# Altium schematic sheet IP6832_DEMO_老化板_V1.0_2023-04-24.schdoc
size 304 x 179 mm
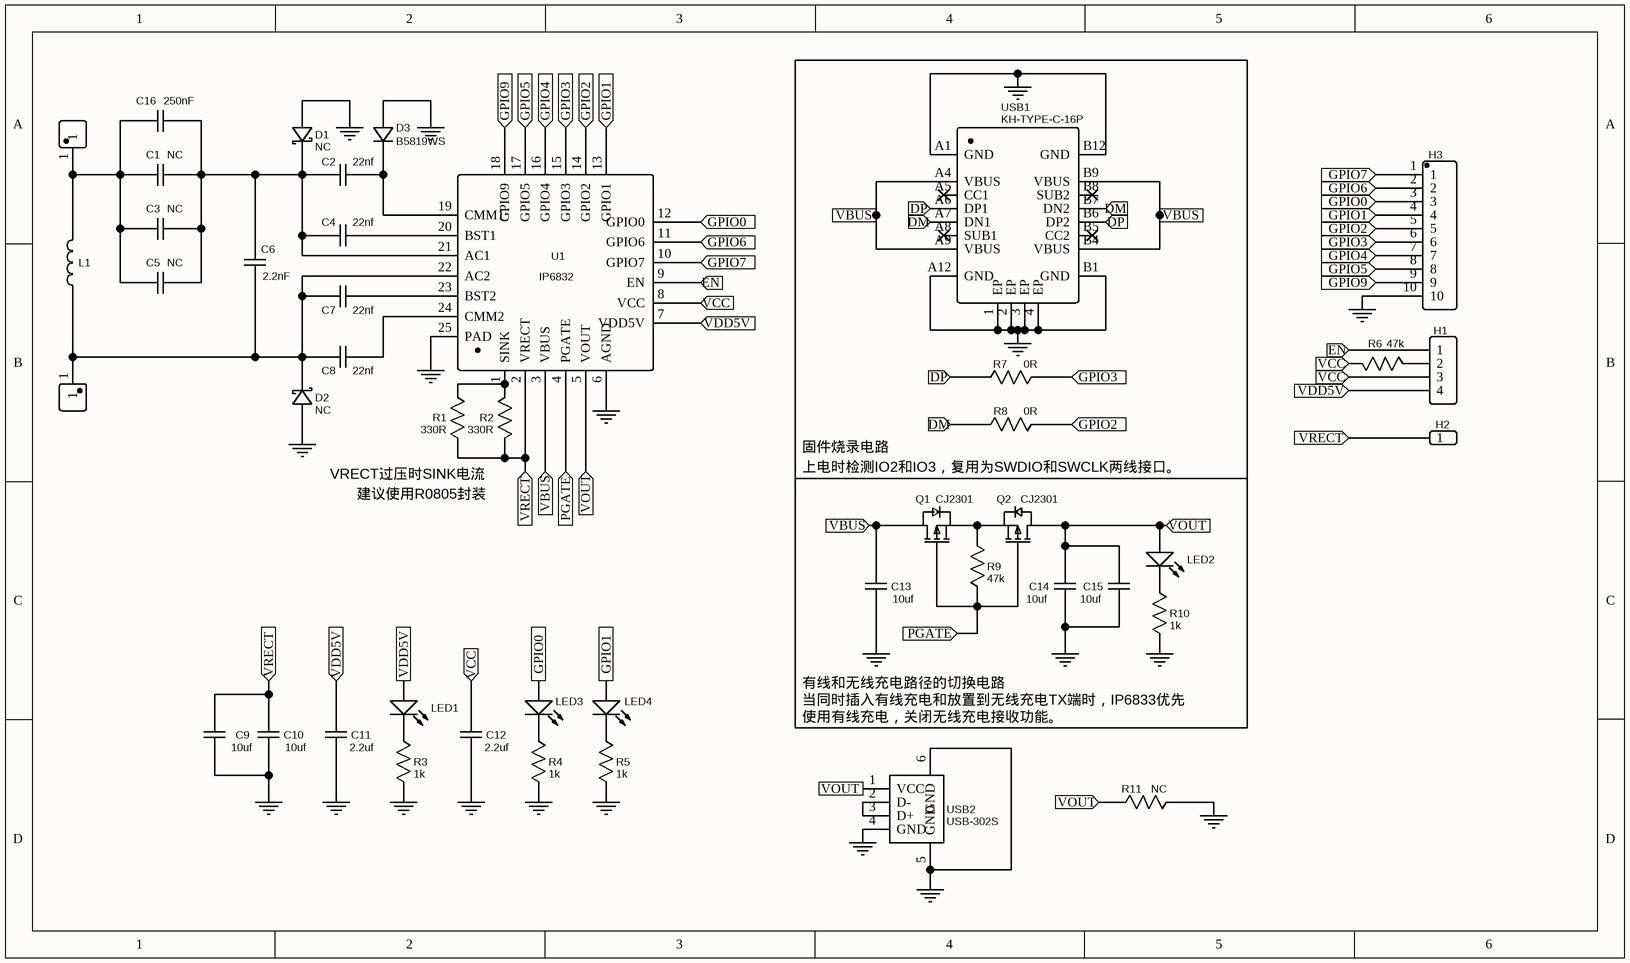
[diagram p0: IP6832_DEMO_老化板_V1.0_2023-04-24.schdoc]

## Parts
C1  NC  [C0603]
C2  22nf  [C0603]
C3  NC  [C0603]
C4  22nf  [C0603]
C5  NC  [C0603]
C6  2.2nF  [C0603]
C7  22nf  [C0603]
C8  22nf  [C0603]
C9  10uf  [C0603]
C10  10uf  [C0603]
C11  2.2uf  [C0603]
C12  2.2uf  [C0603]
C13  10uf  [C0603]
C14  10uf  [C0603]
C15  10uf  [C0603]
C16  250nF  [CAP-TH_L15-W9-P7.50-D0.6]
D1  NC  [SOD-123FL_L2.8-W1.8-LS3.8-R-RD]
D2  NC  [SOD-123FL_L2.8-W1.8-LS3.8-R-RD]
D3  B5819WS  [SOD-323_L1.8-W1.3-LS2.5-RD]
H1  HDR-M-2.54_1x4  [HDR-M-2.54_1X4]  (value not drawn)
H2  Header-Male-2.54_1x1  [HDR-TH_1P-P2.54-V-M]  (value not drawn)
H3  Header-Male-2.54_1x10  [HDR-TH_10P-P2.54-V-M-1]  (value not drawn)
L1  10uH  [IND-SMD_L6.4-W4.1]  (value not drawn)
LED1  LED  [LED0603_RED]  (value not drawn)
LED2  LED  [LED0603_RED]  (value not drawn)
LED3  LED  [LED0603_RED]  (value not drawn)
LED4  LED  [LED0603_RED]  (value not drawn)
Q1  CJ2301  [SOT-23-3_L2.9-W1.3-P1.90-LS2.4-BR]
Q2  CJ2301  [SOT-23-3_L2.9-W1.3-P1.90-LS2.4-BR]
R1  330R  [R0805]
R2  330R  [R0805]
R3  1k  [R0603]
R4  1k  [R0603]
R5  1k  [R0603]
R6  47k  [R0603]
R7  0R  [R0603]
R8  0R  [R0603]
R9  47k  [R0603]
R10  1k  [R0603]
R11  NC  [R_P55]
U1  IP6832  [QFN-24_L4.0-W4.0-P0.50-BL-EP2.5]
U2  TP  [TESTPOINT-TH_BD3.2]  (value not drawn)
U3  TP  [TESTPOINT-TH_BD3.2]  (value not drawn)
USB1  KH-TYPE-C-16P  [USB-C-SMD_KH-TYPE-C-16P]
USB2  USB-302S  [USB-A-SMD_USB-302S]

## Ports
DM (in), DP (in), EN (in), GPIO0 (in), GPIO1 (in), GPIO2 (in), GPIO3 (in), GPIO4 (in), GPIO5 (in), GPIO6 (in), GPIO7 (in), GPIO9 (in), PGATE (in), VBUS (in), VCC (in), VDD5V (in), VOUT (in), VRECT (in)

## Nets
GND: C9.1 C10.1 C11.1 C12.1 C13.1 C14.1 C15.1 D1.1(A) D2.1(A) D3.2(A) H3.10 R3.1 R4.1 R5.1 R10.1 R11.1 U1.6(AGND) U1.25(PAD) USB1.1(EP) USB1.2(EP) USB1.3(EP) USB1.4(EP) USB1.A1(GND) USB1.A12(GND) USB1.B1(GND) USB1.B12(GND) USB2.4(GND) USB2.5(GND) USB2.6(GND)
DM: R8.2 USB1.A7(DN1) USB1.B7(DN2) ; port DM
DP: R7.2 USB1.A6(DP1) USB1.B6(DP2) ; port DP
EN: H1.1 U1.9(EN) ; port EN
GPIO0: H3.3 LED3.1(A) U1.12(GPIO0) ; port GPIO0
GPIO1: H3.4 LED4.1(A) U1.13(GPIO1) ; port GPIO1
GPIO2: H3.5 R8.1 U1.14(GPIO2) ; port GPIO2
GPIO3: H3.6 R7.1 U1.15(GPIO3) ; port GPIO3
GPIO4: H3.7 U1.16(GPIO4) ; port GPIO4
GPIO5: H3.8 U1.17(GPIO5) ; port GPIO5
GPIO6: H3.2 U1.11(GPIO6) ; port GPIO6
GPIO7: H3.1 U1.10(GPIO7) ; port GPIO7
GPIO9: H3.9 U1.18(GPIO9) ; port GPIO9
PGATE: Q1.1(G) Q2.1(G) R9.1 U1.4(PGATE) ; port PGATE
VBUS: C13.2 Q1.3(D) U1.3(VBUS) USB1.A4(VBUS) USB1.A9(VBUS) USB1.B4(VBUS) USB1.B9(VBUS) ; port VBUS
VCC: C12.2 H1.3 R6.1 U1.8(VCC) ; port VCC
VDD5V: C11.2 H1.4 LED1.1(A) U1.7(VDD5V) ; port VDD5V
VOUT: C14.2 C15.2 LED2.1(A) Q2.3(D) R11.2 U1.5(VOUT) USB2.1(VCC) ; port VOUT
VRECT: C9.2 C10.2 H2.1 R1.1 R2.1 U1.2(VRECT) ; port VRECT
NetC1_1: C1.1 C2.2 C3.1 C4.2 C5.1 C6.2 C16.2 D1.2(K) U1.21(AC1)
NetC1_2: C1.2 C3.2 C5.2 C16.1 L1.2 U2.1
NetC2_1: C2.1 D3.1(C) U1.19(CMM1)
NetC4_1: C4.1 U1.20(BST1)
NetC6_1: C6.1 C7.1 C8.1 D2.2(K) L1.1 U1.22(AC2) U3.1
NetC7_2: C7.2 U1.23(BST2)
NetC8_2: C8.2 U1.24(CMM2)
NetH1_2: H1.2 R6.2
NetLED1_2: LED1.2(K) R3.2
NetLED2_2: LED2.2(K) R10.2
NetLED3_2: LED3.2(K) R4.2
NetLED4_2: LED4.2(K) R5.2
NetQ1_2: Q1.2(S) Q2.2(S) R9.2
NetR1_2: R1.2 R2.2 U1.1(SINK)
NetUSB2_2: USB2.2(D-) USB2.3(D+)

Not connected (* = marked no-connect by the designer): USB1 A5(CC1)* A8(SUB1)* B5(CC2)* B8(SUB2)*

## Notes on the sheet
- (near R1) VRECT过压时SINK电流
- 建议使用R0805封装
- 固件烧录电路
- 上电时检测IO2和IO3，复用为SWDIO和SWCLK两线接口。
- 有线和无线充电路径的切换电路
- 当同时插入有线充电和放置到无线充电TX端时，IP6833优先
- (near USB2) 使用有线充电，关闭无线充电接收功能。

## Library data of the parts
C1 C3 C5 = NC: nameAlias: Value(F); Contributor: LCEDA_Lib
C2 C4 C7 C8 = 22nf: nameAlias: Value(F); Contributor: LCEDA_Lib
C6 = 2.2nF: nameAlias: Value(F); Contributor: LCEDA_Lib
C9 C10 C13-C15 = 10uf: nameAlias: Value(F); Contributor: LCEDA_Lib
C11 C12 = 2.2uf: nameAlias: Value(F); Contributor: LCEDA_Lib
C16 = 250nF: BOM_Manufacturer: KNSCHA; BOM_Manufacturer Part: MPP104J2J07AJ22600; nameAlias: Capacitance; Contributor: LCSC
D1 D2 = NC: BOM_Manufacturer: FTR; BOM_Manufacturer Part: SMF15A; Contributor: LCSC
D3 = B5819WS: BOM_Manufacturer: CJ(江苏长电/长晶); Contributor: LCSC
H1 = HDR-M-2.54_1x4: Contributor: LCEDA_Lib
H2 = Header-Male-2.54_1x1: BOM_Manufacturer: ReliaPro
H3 = Header-Male-2.54_1x10: BOM_Manufacturer Part: 2.54-1*10P针; BOM_Manufacturer: BOOMELE(博穆精密)
L1 = 10uH: BOM_Manufacturer: COILMX; BOM_Manufacturer Part: MPA252012S6R8M; nameAlias: Inductance; Contributor: LCSC
LED1-LED4 = LED: Contributor: tycc
Q1 Q2 = CJ2301: BOM_Manufacturer: CJ（江苏长电/长晶）; Contributor: LCSC
R1 R2 = 330R: nameAlias: Value(Ω); Contributor: LCEDA_Lib
R3-R5 R10 = 1k: nameAlias: Value(Ω); Contributor: LCEDA_Lib
R6 R9 = 47k: nameAlias: Value(Ω); Contributor: LCEDA_Lib
R7 R8 = 0R: nameAlias: Value(Ω); Contributor: LCEDA_Lib
R11 = NC: nameAlias: Value(Ω); Contributor: LCEDA_Lib
U1 = IP6832: Contributor: Su_Yuan
U2 U3 = TP: BOM_Manufacturer: null; BOM_Manufacturer Part: TP-红色测试点; Contributor: lcsc
USB1 = KH-TYPE-C-16P: BOM_Manufacturer: Shenzhen Kinghelm Elec; Contributor: LCSC
USB2 = USB-302S: BOM_Manufacturer: SOFNG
